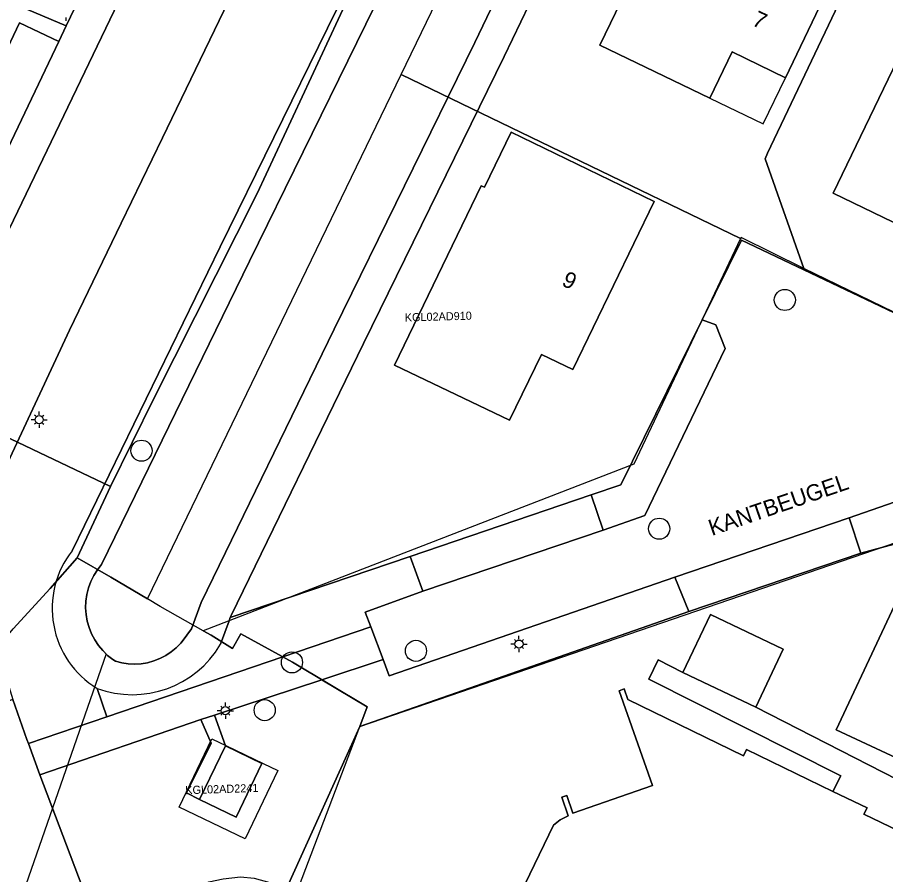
# Model space of a CAD drawing. Extents: x 124901 to 125496, y 515369 to 515789.
# Drawn here: x 125324.5 to 125378, y 515408.1 to 515460.9 of the extents above; entities that cross this region are included whole.
import ezdxf

# ---------------------------------------------------------------- set-up
doc = ezdxf.new("R2010")
doc.units = 0
for name, color, linetype in [('Berm', 7, 'Continuous'), ('Gebouw', 7, 'Continuous'), ('Kunstwerkdeel', 7, 'Continuous'), ('Lichtmast', 7, 'Continuous'), ('Luifel', 7, 'Continuous'), ('Onbegroeid terrein', 7, 'Continuous'), ('Parkeren', 7, 'Continuous'), ('Perceelnummers', 7, 'Continuous'), ('Perceelsgrenzen', 7, 'Continuous'), ('Putten', 7, 'Continuous'), ('Scheiding', 7, 'Continuous'), ('Teksten', 7, 'Continuous'), ('Vegetatie', 7, 'Continuous'), ('Voetpad', 7, 'Continuous'), ('Water', 7, 'Continuous'), ('Wegen drempel verkeerseiland', 7, 'Continuous'), ('Wegen lokale weg', 7, 'Continuous')]:
    doc.layers.add(name, color=color, linetype=linetype)

msp = doc.modelspace()

# ---------------------------------------------------------------- linework, layer by layer
at = {"layer": 'Berm'}
for points in [[(125361.382, 515506.353), (125358.341, 515500), (125356.132, 515495.386), (125352.081, 515486.922), (125350.047, 515487.919), (125347.883, 515483.449), (125340.998, 515469.097), (125333.443, 515453.439), (125330.916, 515448.196), (125327.735, 515441.596), (125323.653, 515432.831)], [(125327.894, 515428.026), (125337.01, 515446.725), (125346.912, 515466.932), (125357.851, 515489.665), (125362.738, 515500), (125363.142, 515500.855), (125364.886, 515504.544), (125364.088, 515504.922), (125361.382, 515506.353)], [(125322.636, 515424.008), (125324.235, 515418.867), (125325.106, 515416.399), (125325.195, 515416.155), (125330.022, 515417.799), (125329.425, 515419.553)]]:
    msp.add_lwpolyline(points, dxfattribs=at)
msp.add_arc((125332.419, 515424.469), 5.756, 141.8287, 238.656, dxfattribs=at)
at = {"layer": 'Gebouw'}
for points in [[(125374.287, 515462.54), (125376.4, 515466.92), (125370.04, 515469.98), (125368.18, 515466.11), (125364.58, 515467.84), (125360.37, 515459.14), (125367.132, 515455.88), (125368.504, 515458.725), (125371.79, 515457.14), (125374.35, 515462.51)], [(125384.62, 515458.25), (125383.768, 515456.476), (125378.95, 515458.79), (125374.731, 515450.024), (125381.47, 515446.78), (125383.268, 515450.44), (125386.83, 515448.69), (125390.16, 515455.54)], [(125356.77, 515440.112), (125358.706, 515439.175), (125363.716, 515449.53), (125354.91, 515453.79), (125353.259, 515450.393), (125353.06, 515450.49), (125347.72, 515439.45), (125354.81, 515436.06)], [(125365.483, 515420.533), (125369.957, 515418.385), (125371.65, 515421.956), (125367.176, 515424.108)]]:
    msp.add_lwpolyline(points, close=True, dxfattribs=at)
for points in [[(125369.39, 515415.78), (125369.201, 515415.396), (125362.079, 515418.876), (125361.86, 515419.52), (125361.55, 515419.41), (125363.598, 515413.583), (125358.714, 515411.866), (125358.33, 515412.96), (125358.02, 515412.85), (125358.42, 515411.7), (125357.93, 515411.45), (125357.51, 515411.13), (125347.289, 515389.969), (125347.1, 515390.06), (125346.99, 515389.77), (125350.825, 515387.907), (125349.87, 515385.94)], [(125372.005, 515373.543), (125369.392, 515381.106), (125374.299, 515382.802), (125374.757, 515381.475), (125375.06, 515381.58), (125374.601, 515382.911), (125376.54, 515383.58), (125375.324, 515387.078), (125380.02, 515388.71), (125380.89, 515391.42), (125377.294, 515393.154), (125380.88, 515400.59), (125380.493, 515400.777), (125384.09, 515408.22), (125376.623, 515411.811), (125376.81, 515412.2), (125374.711, 515413.213), (125369.39, 515415.78)]]:
    msp.add_lwpolyline(points, dxfattribs=at)
at = {"layer": 'Kunstwerkdeel'}
msp.add_lwpolyline([(125329.978, 515421.675), (125320.056, 515393.181)], dxfattribs=at)
at = {"layer": 'Lichtmast'}
for p, q in [((125327.502, 515460.846), (125327.502, 515460.646)), ((125325.649, 515436.301), (125325.579, 515436.372)), ((125325.861, 515436.389), (125325.861, 515436.589)), ((125326.073, 515436.301), (125326.144, 515436.373)), ((125325.561, 515436.09), (125325.361, 515436.089)), ((125325.649, 515435.877), (125325.577, 515435.806)), ((125325.861, 515435.789), (125325.861, 515435.589)), ((125326.073, 515435.877), (125326.143, 515435.806)), ((125326.161, 515436.089), (125326.361, 515436.089)), ((125355.09, 515422.28), (125354.89, 515422.279)), ((125355.178, 515422.491), (125355.108, 515422.562)), ((125355.39, 515422.579), (125355.39, 515422.779)), ((125355.602, 515422.491), (125355.673, 515422.563)), ((125355.69, 515422.279), (125355.89, 515422.279)), ((125355.178, 515422.067), (125355.106, 515421.996)), ((125355.39, 515421.979), (125355.39, 515421.779)), ((125355.602, 515422.067), (125355.672, 515421.996)), ((125337.32, 515418.478), (125337.32, 515418.678)), ((125337.02, 515418.179), (125336.82, 515418.178)), ((125337.108, 515418.39), (125337.038, 515418.461)), ((125337.532, 515418.39), (125337.603, 515418.462)), ((125337.62, 515418.178), (125337.82, 515418.178)), ((125337.108, 515417.966), (125337.036, 515417.895)), ((125337.32, 515417.878), (125337.32, 515417.678)), ((125337.532, 515417.966), (125337.602, 515417.895))]:
    msp.add_line(p, q, dxfattribs=at)
for centre in [(125325.861, 515436.089), (125355.39, 515422.279), (125337.32, 515418.178)]:
    msp.add_circle(centre, 0.25, dxfattribs=at)
at = {"layer": 'Luifel'}
msp.add_lwpolyline([(125368.504, 515458.725), (125367.132, 515455.88), (125370.418, 515454.295), (125371.79, 515457.14)], close=True, dxfattribs=at)
at = {"layer": 'Onbegroeid terrein'}
for points in [[(125423.349, 515476.349), (125375.06, 515499.729), (125374.488, 515500), (125374.446, 515500.02), (125374.437, 515500), (125373.074, 515497.101), (125363.713, 515477.679), (125354.474, 515458.437), (125345.815, 515440.777), (125337.674, 515424.045), (125337.623, 515423.908), (125348.697, 515427.677), (125359.827, 515431.465), (125361.663, 515432.09), (125366.656, 515442.245), (125369.078, 515447.143), (125383.134, 515440.443)], [(125379.218, 515414.988), (125374.915, 515417.009), (125380.523, 515428.985), (125376.433, 515427.864), (125365.843, 515424.279), (125345.594, 515417.203), (125341.107, 515407.269)], [(125369.201, 515415.396), (125369.39, 515415.78), (125374.711, 515413.213), (125375.203, 515414.177), (125363.387, 515420.112), (125363.965, 515421.3), (125365.483, 515420.533), (125367.176, 515424.108), (125371.65, 515421.956), (125369.957, 515418.385), (125378.674, 515413.948)], [(125349.87, 515385.94), (125350.825, 515387.907), (125346.99, 515389.77), (125347.1, 515390.06), (125347.289, 515389.969), (125357.51, 515411.13), (125357.93, 515411.45), (125358.42, 515411.7), (125358.02, 515412.85), (125358.33, 515412.96), (125358.714, 515411.866), (125363.598, 515413.583), (125361.55, 515419.41), (125361.86, 515419.52), (125362.079, 515418.876), (125369.201, 515415.396)]]:
    msp.add_lwpolyline(points, dxfattribs=at)
for points in [[(125376.4, 515466.92), (125374.287, 515462.54), (125374.35, 515462.51), (125371.79, 515457.14), (125368.504, 515458.725), (125367.132, 515455.88), (125360.37, 515459.14), (125364.58, 515467.84), (125368.18, 515466.11), (125370.04, 515469.98)], [(125383.768, 515456.476), (125384.62, 515458.25), (125390.16, 515455.54), (125386.83, 515448.69), (125383.268, 515450.44), (125381.47, 515446.78), (125374.731, 515450.024), (125378.95, 515458.79)], [(125358.706, 515439.175), (125356.77, 515440.112), (125354.81, 515436.06), (125347.72, 515439.45), (125353.06, 515450.49), (125353.259, 515450.393), (125354.91, 515453.79), (125363.716, 515449.53)], [(125337.338, 515416.013), (125335.734, 515412.721), (125337.991, 515411.621), (125339.566, 515414.931)]]:
    msp.add_lwpolyline(points, close=True, dxfattribs=at)
at = {"layer": 'Parkeren'}
for points in [[(125327.069, 515459.363), (125321.82, 515448.4), (125321.344, 515447.407), (125320.601, 515445.855), (125320.611, 515445.794), (125320.771, 515445.648), (125322.459, 515444.797), (125322.468, 515444.71), (125322.447, 515444.61), (125338.718, 515478.436), (125338.65, 515478.425), (125338.571, 515478.432), (125338.447, 515478.456), (125336.857, 515479.152), (125336.716, 515479.168), (125336.595, 515479.085), (125336.512, 515478.971), (125332.233, 515470.132), (125331.708, 515469.046), (125331.383, 515468.375), (125327.533, 515460.333)], [(125360.576, 515429.287), (125359.827, 515431.465), (125348.697, 515427.677), (125349.482, 515425.537)], [(125364.988, 515426.388), (125365.843, 515424.279), (125376.433, 515427.864), (125375.706, 515430.042)]]:
    msp.add_lwpolyline(points, close=True, dxfattribs=at)
for points in [[(125380.523, 515428.985), (125374.915, 515417.009), (125379.218, 515414.988)], [(125378.674, 515413.948), (125369.957, 515418.385), (125365.483, 515420.533), (125363.965, 515421.3), (125363.387, 515420.112), (125375.203, 515414.177), (125374.711, 515413.213), (125376.81, 515412.2), (125376.623, 515411.811), (125384.09, 515408.22)]]:
    msp.add_lwpolyline(points, dxfattribs=at)
at = {"layer": 'Perceelsgrenzen'}
for points in [[(125423.088, 515612.915), (125352.068, 515590.151), (125354.844, 515582.98), (125359.632, 515568.992), (125367.282, 515546.531), (125373.39, 515529.447), (125374.833, 515525.657), (125370.2, 515515.457), (125361.451, 515496.989), (125354.147, 515481.936), (125345.37, 515463.116), (125339.28, 515450.017), (125332.914, 515437.391), (125330.261, 515431.98), (125328.194, 515427.596), (125330.281, 515426.402), (125332.521, 515425.055), (125348.134, 515457.345), (125358.716, 515479.229), (125369.827, 515502.206), (125375.06, 515499.729), (125385.193, 515494.823)], [(125266.73, 515462.423), (125271.601, 515460.092), (125276.62, 515457.69), (125272.23, 515448.55), (125264.92, 515433.45), (125270.716, 515430.64), (125274.12, 515437.76), (125278.94, 515435.44), (125279.33, 515436.25), (125284.59, 515433.74), (125292.38, 515450.04), (125312.72, 515440.33), (125330.261, 515431.98), (125332.914, 515437.391), (125339.28, 515450.017), (125345.37, 515463.116)], [(125383.955, 515440.045), (125372.915, 515445.397), (125369.062, 515447.298), (125369.032, 515447.235), (125362.46, 515433.35), (125335.946, 515423.097), (125336.439, 515422.819), (125337.767, 515422.004), (125338.281, 515422.912), (125341.448, 515421.165), (125346.053, 515418.41), (125345.594, 515417.203), (125386.949, 515431.401)], [(125329.637, 515373.543), (125321.13, 515396.81), (125308.38, 515404.21), (125310.17, 515407.79), (125313.051, 515410.892), (125315.603, 515413.311), (125318.469, 515416.658), (125321.341, 515419.695), (125324.27, 515423.207), (125326.529, 515425.692), (125328.194, 515427.596), (125330.261, 515431.98), (125312.72, 515440.33), (125296.52, 515406.57), (125290.24, 515409.58), (125288.88, 515406.8), (125279.42, 515411.33)], [(125347.273, 515373.543), (125347.035, 515373.992), (125346.605, 515374.956), (125346.243, 515375.947), (125345.95, 515376.96), (125337.56, 515398.86), (125339.28, 515400.59), (125345.594, 515417.203), (125386.949, 515431.401), (125394.052, 515427.9), (125396.029, 515421.819), (125398.444, 515414.714), (125401.327, 515406.13), (125385.649, 515373.543)], [(125347.273, 515373.543), (125347.035, 515373.992), (125346.605, 515374.956), (125346.243, 515375.947), (125345.95, 515376.96), (125337.56, 515398.86), (125339.28, 515400.59), (125345.594, 515417.203), (125346.053, 515418.41), (125341.448, 515421.165), (125338.281, 515422.912), (125337.767, 515422.004), (125336.439, 515422.819), (125335.946, 515423.097), (125333.303, 515424.585), (125332.521, 515425.055), (125330.281, 515426.402), (125328.194, 515427.596), (125326.529, 515425.692), (125324.27, 515423.207)]]:
    msp.add_lwpolyline(points, dxfattribs=at)
for points in [[(125374.07, 515471.84), (125378.816, 515469.556), (125370.68, 515452.487), (125370.542, 515452.147), (125372.915, 515445.397), (125369.062, 515447.298), (125369.032, 515447.235), (125348.134, 515457.345), (125358.716, 515479.229)], [(125394.62, 515461.95), (125383.955, 515440.045), (125372.915, 515445.397), (125370.542, 515452.147), (125370.68, 515452.487), (125378.816, 515469.556), (125386.705, 515465.759)], [(125332.521, 515425.055), (125348.134, 515457.345), (125369.032, 515447.235), (125362.46, 515433.35), (125335.946, 515423.097), (125333.303, 515424.585)], [(125334.483, 515412.241), (125336.483, 515416.451), (125337.386, 515416.022), (125339.654, 515414.936), (125340.556, 515414.505), (125338.539, 515410.294)], [(125334.483, 515412.241), (125336.483, 515416.451), (125337.386, 515416.022), (125339.654, 515414.936), (125340.556, 515414.505), (125338.539, 515410.294)]]:
    msp.add_lwpolyline(points, close=True, dxfattribs=at)
at = {"layer": 'Putten'}
for centre in [(125371.75, 515443.46), (125332.16, 515434.18), (125364.02, 515429.38), (125349.05, 515421.86), (125341.42, 515421.15), (125339.74, 515418.21)]:
    msp.add_circle(centre, 0.65, dxfattribs=at)
at = {"layer": 'Scheiding'}
for points in [[(125329.706, 515427.178), (125338.807, 515445.847), (125348.711, 515466.058), (125359.656, 515488.804), (125364.95, 515500)], [(125372.227, 515500), (125371.268, 515497.961), (125361.911, 515478.546), (125352.675, 515459.31), (125344.018, 515441.655), (125335.832, 515424.831), (125335.238, 515423.221), (125334.665, 515422.443)], [(125329.706, 515427.178), (125329.449, 515426.852), (125329.228, 515426.501), (125329.044, 515426.129), (125328.9, 515425.74), (125328.798, 515425.338), (125328.739, 515424.927), (125328.722, 515424.512), (125328.749, 515424.098), (125328.82, 515423.689), (125328.932, 515423.29), (125329.086, 515422.904), (125329.279, 515422.537), (125329.51, 515422.192), (125329.775, 515421.873), (125330.072, 515421.583), (125330.398, 515421.326), (125330.561, 515421.217)], [(125330.561, 515421.217), (125330.948, 515421.117), (125331.344, 515421.058), (125331.744, 515421.041), (125332.143, 515421.066), (125332.537, 515421.132), (125332.923, 515421.24), (125333.295, 515421.386), (125333.649, 515421.571), (125333.983, 515421.793), (125334.291, 515422.047), (125334.571, 515422.333), (125334.665, 515422.443)]]:
    msp.add_lwpolyline(points, dxfattribs=at)
at = {"layer": 'Vegetatie'}
for points in [[(125327.533, 515460.333), (125331.383, 515468.375), (125331.708, 515469.046), (125329.36, 515470.225), (125325.141, 515461.339)], [(125321.82, 515448.4), (125327.069, 515459.363), (125324.645, 515460.515), (125319.427, 515449.511)], [(125359.827, 515431.465), (125360.576, 515429.287), (125363.142, 515430.186), (125368.078, 515440.464), (125367.498, 515441.937), (125366.656, 515442.245), (125361.663, 515432.09)], [(125347.027, 515421.333), (125343.255, 515420.084), (125346.053, 515418.41), (125345.594, 515417.203), (125365.843, 515424.279), (125364.988, 515426.388), (125347.407, 515420.321)], [(125346.053, 515418.41), (125343.255, 515420.084), (125336.646, 515417.896), (125337.338, 515416.013), (125339.566, 515414.931), (125337.991, 515411.621), (125335.734, 515412.721), (125334.932, 515413.112), (125336.441, 515416.184), (125335.816, 515417.635), (125325.904, 515414.222), (125329.923, 515403.616), (125333.439, 515405.192), (125333.443, 515405.2), (125334.038, 515405.862), (125334.936, 515406.868), (125335.598, 515407.308), (125336.309, 515407.634), (125337.183, 515407.832), (125338.245, 515407.953), (125339.096, 515407.877), (125340.06, 515407.603), (125341.107, 515407.269), (125345.594, 515417.203)]]:
    msp.add_lwpolyline(points, close=True, dxfattribs=at)
for points in [[(125385.959, 515433.617), (125375.706, 515430.042), (125376.433, 515427.864), (125380.523, 515428.985)], [(125349.482, 515425.537), (125348.697, 515427.677), (125337.623, 515423.908), (125337.547, 515423.702), (125337.016, 515422.263)], [(125329.425, 515419.553), (125330.022, 515417.799), (125346.275, 515423.336), (125345.933, 515424.247), (125349.482, 515425.537)]]:
    msp.add_lwpolyline(points, dxfattribs=at)
msp.add_arc((125331.603, 515425.438), 6.275, 249.6867, 329.6066, dxfattribs=at)
at = {"layer": 'Voetpad'}
msp.add_lwpolyline([(125325.794, 515467.439), (125317.296, 515449.771), (125315.082, 515445.025), (125314.53, 515443.843), (125316.351, 515442.981), (125318.935, 515448.499), (125321.344, 515447.407), (125321.82, 515448.4), (125319.427, 515449.511), (125324.645, 515460.515), (125327.069, 515459.363), (125327.533, 515460.333), (125325.141, 515461.339)], dxfattribs=at)
for points in [[(125347.027, 515421.333), (125346.275, 515423.336), (125330.022, 515417.799), (125325.195, 515416.155), (125325.904, 515414.222), (125335.816, 515417.635), (125336.646, 515417.896), (125343.255, 515420.084)], [(125335.734, 515412.721), (125337.338, 515416.013), (125336.646, 515417.896), (125335.816, 515417.635), (125336.441, 515416.184), (125334.932, 515413.112)]]:
    msp.add_lwpolyline(points, close=True, dxfattribs=at)
at = {"layer": 'Water'}
for points in [[(125364.58, 515571.173), (125365.658, 515568.312), (125371.741, 515551.276), (125374.806, 515542.701), (125376.571, 515537.55), (125377.004, 515535.615), (125377.157, 515534.454), (125377.232, 515533.336), (125377.185, 515532.051), (125377.068, 515530.536), (125376.824, 515529.274), (125376.357, 515528.013), (125374.572, 515524.721), (125368.756, 515512.727), (125365.599, 515506.052), (125364.886, 515504.544), (125363.142, 515500.855), (125362.738, 515500), (125357.851, 515489.665), (125346.912, 515466.932), (125337.01, 515446.725), (125327.894, 515428.026)], [(125337.623, 515423.908), (125337.674, 515424.045), (125345.815, 515440.777), (125354.474, 515458.437), (125363.713, 515477.679), (125373.074, 515497.101), (125374.437, 515500), (125374.446, 515500.02), (125375.206, 515501.532), (125378.052, 515507.906), (125379.264, 515508.455), (125383.37, 515517.481), (125388.202, 515532.111), (125393.5, 515547.461), (125387.194, 515549.705)], [(125348.711, 515466.058), (125338.807, 515445.847), (125329.706, 515427.178), (125329.449, 515426.852), (125329.228, 515426.501), (125329.044, 515426.129), (125328.9, 515425.74), (125328.798, 515425.337), (125328.738, 515424.927), (125328.722, 515424.512), (125328.749, 515424.098), (125328.819, 515423.689), (125328.932, 515423.29), (125329.086, 515422.904), (125329.279, 515422.537), (125329.51, 515422.192), (125329.775, 515421.873), (125330.072, 515421.583), (125330.398, 515421.326), (125330.561, 515421.217), (125330.948, 515421.117), (125331.344, 515421.058), (125331.744, 515421.041), (125332.143, 515421.066), (125332.537, 515421.132), (125332.923, 515421.24), (125333.295, 515421.387), (125333.649, 515421.571), (125333.983, 515421.793), (125334.291, 515422.047), (125334.571, 515422.333), (125334.665, 515422.443), (125335.238, 515423.221), (125335.832, 515424.831), (125344.018, 515441.655), (125352.675, 515459.31), (125361.911, 515478.546)], [(125361.911, 515478.546), (125352.675, 515459.31), (125344.018, 515441.655), (125335.832, 515424.831), (125335.238, 515423.221), (125334.665, 515422.443), (125334.571, 515422.333), (125334.291, 515422.047), (125333.983, 515421.793), (125333.649, 515421.571), (125333.295, 515421.387), (125332.923, 515421.24), (125332.537, 515421.132), (125332.143, 515421.066), (125331.744, 515421.041), (125331.344, 515421.058), (125330.948, 515421.117), (125330.561, 515421.217), (125330.398, 515421.326), (125330.072, 515421.583), (125329.775, 515421.873), (125329.51, 515422.192), (125329.279, 515422.537), (125329.086, 515422.904), (125328.932, 515423.29), (125328.819, 515423.689), (125328.749, 515424.098), (125328.722, 515424.512), (125328.738, 515424.927), (125328.798, 515425.337), (125328.9, 515425.74), (125329.044, 515426.129), (125329.228, 515426.501), (125329.449, 515426.852), (125329.706, 515427.178), (125338.807, 515445.847), (125348.711, 515466.058)], [(125337.016, 515422.263), (125337.547, 515423.702), (125337.623, 515423.908)]]:
    msp.add_lwpolyline(points, dxfattribs=at)
for centre, radius, start, end in [((125332.419, 515424.469), 5.756, 141.8287, 238.656), ((125331.603, 515425.438), 6.275, 249.6867, 329.6066)]:
    msp.add_arc(centre, radius, start, end, dxfattribs=at)
at = {"layer": 'Wegen drempel verkeerseiland'}
msp.add_lwpolyline([(125333.01, 515395.297), (125330.728, 515401.491), (125329.923, 515403.616), (125325.904, 515414.222), (125325.195, 515416.155), (125325.106, 515416.399), (125324.235, 515418.867), (125319.117, 515417.06), (125319.92, 515414.8), (125320.031, 515414.443), (125320.732, 515412.187), (125321.272, 515410.449)], dxfattribs=at)
at = {"layer": 'Wegen lokale weg'}
for points in [[(125323.653, 515432.831), (125327.735, 515441.596), (125330.916, 515448.196), (125333.443, 515453.439), (125340.998, 515469.097), (125347.883, 515483.449), (125350.047, 515487.919), (125354.111, 515496.359), (125348.614, 515499.006), (125346.984, 515495.648), (125339.36, 515479.68), (125338.718, 515478.436), (125322.447, 515444.61)], [(125383.134, 515440.443), (125369.078, 515447.143), (125366.656, 515442.245), (125367.498, 515441.937), (125368.078, 515440.464), (125363.142, 515430.186), (125360.576, 515429.287), (125349.482, 515425.537), (125345.933, 515424.247), (125346.275, 515423.336), (125347.027, 515421.333), (125347.407, 515420.321), (125364.988, 515426.388), (125375.706, 515430.042), (125385.959, 515433.617)]]:
    msp.add_lwpolyline(points, dxfattribs=at)

# ---------------------------------------------------------------- texts
at = {"layer": 'Perceelnummers'}
for s, rotation, p in [('KGL02AD910', 1.6339, (125348.368, 515442.13)), ('KGL02AD2241', 1.832, (125334.862, 515413.036))]:
    msp.add_text(s, height=0.5, rotation=rotation, dxfattribs=at).set_placement(p)
at = {"layer": 'Teksten'}
for s, rotation, p in [('7', 334.5, (125369.666, 515460.403)), ('9', 334.2, (125357.958, 515444.381)), ('KANTBEUGEL', 18.9, (125367.257, 515428.93))]:
    msp.add_text(s, height=1, rotation=rotation, dxfattribs=at).set_placement(p)

doc.saveas('drawing.dxf')
